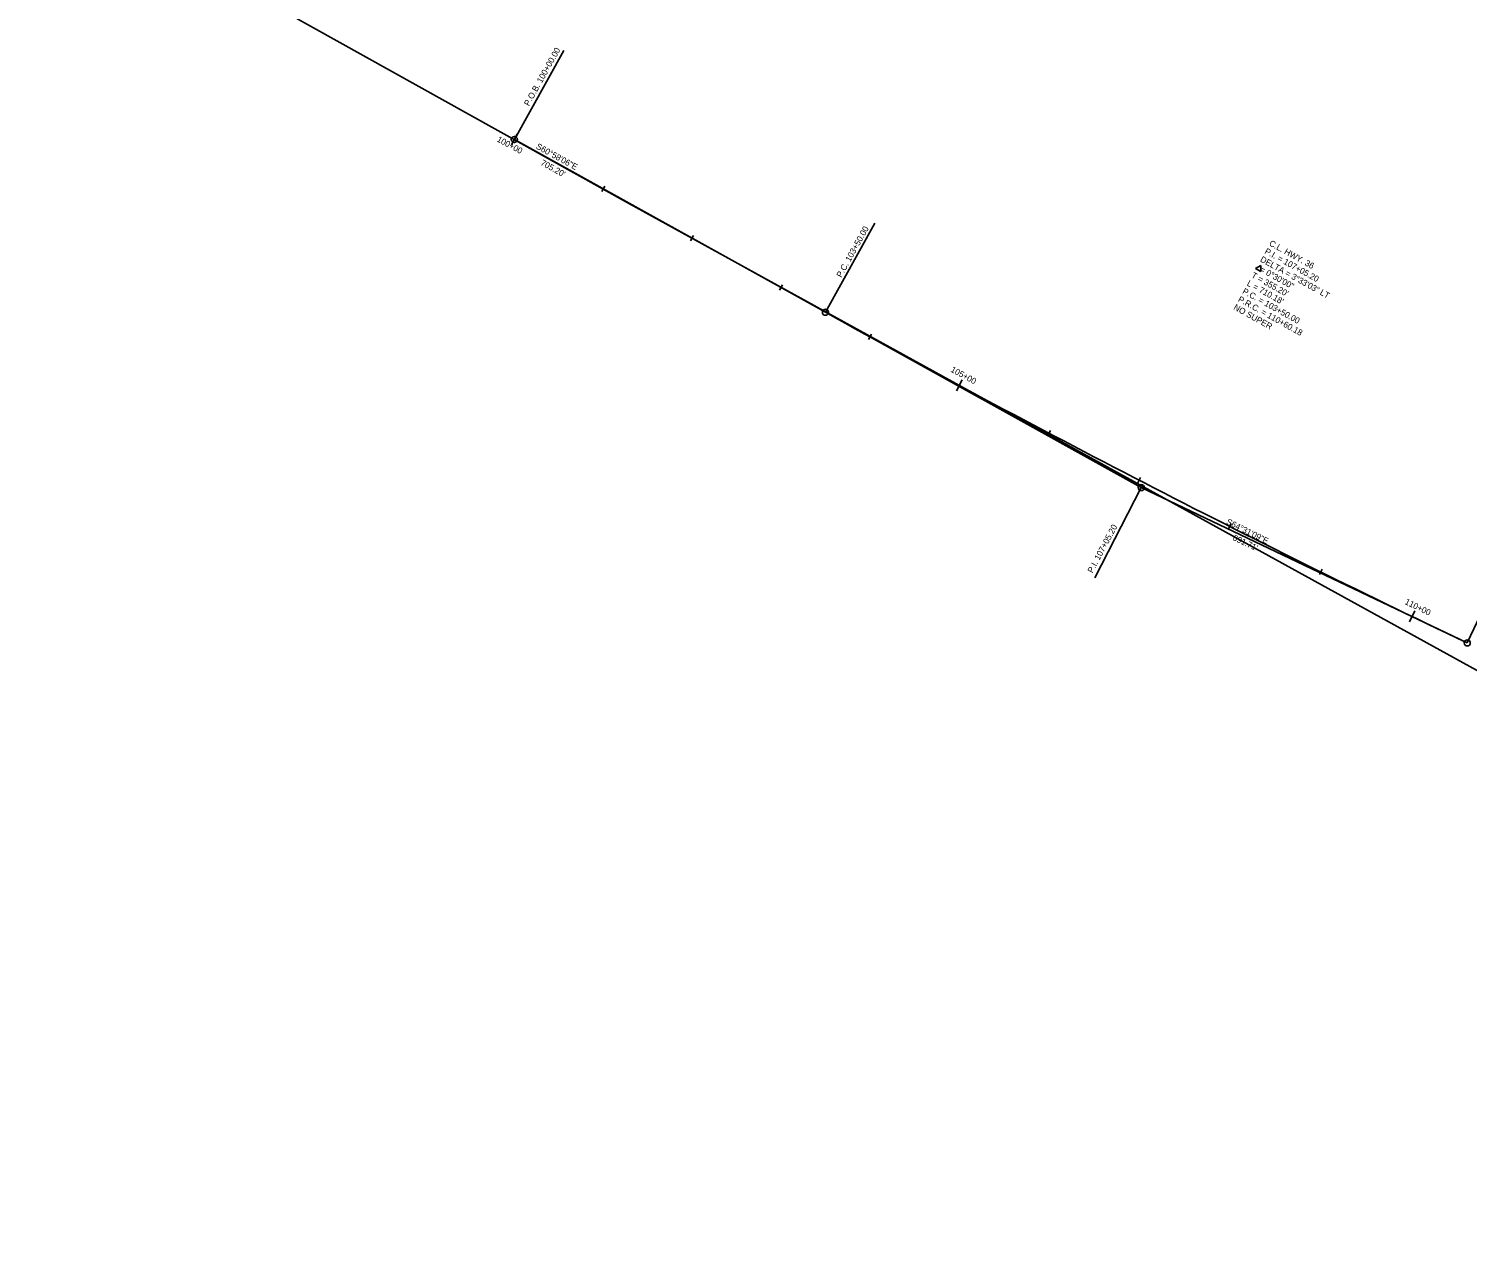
# Model space of a CAD drawing. Extents: x 1451272 to 1457767, y 301145 to 304591.
# Drawn here: x 1452687 to 1454102, y 302567 to 303775 of the extents above; entities that cross this region are included whole.
import ezdxf

# ---------------------------------------------------------------- set-up
doc = ezdxf.new("R2010")
doc.units = 0
for name, color, linetype in [('CL_Highway_1', 7, 'Continuous'), ('CL_Highway_1_text', 7, 'Continuous'), ('CL_Tangent', 7, 'Continuous'), ('CL_Tangent_Length', 7, 'Continuous'), ('CurveData_100', 7, 'Continuous'), ('PCPT_100_CL_ALT1', 7, 'Continuous'), ('PCPT_100_CL_Annot', 7, 'Continuous'), ('PI_100_CL_ALT1', 7, 'Continuous'), ('PI_100_CL_Annot', 7, 'Continuous'), ('Point_CL_Highway_2', 7, 'Continuous'), ('RD_Exist_CL', 7, 'Continuous'), ('STA_100_CL', 7, 'Continuous'), ('TICK_100_CL', 7, 'Continuous')]:
    doc.layers.add(name, color=color, linetype=linetype)

msp = doc.modelspace()

# ---------------------------------------------------------------- linework, layer by layer
at = {"layer": 'CL_Highway_1'}
msp.add_line((1453164.7, 303666.6), (1453470.7, 303496.7), dxfattribs=at)
msp.add_line((1453164.7, 303666.6), (1453470.7, 303496.7), dxfattribs=at)
msp.add_line((1453164.7, 303666.6), (1453470.7, 303496.7), dxfattribs=at)
msp.add_line((1453164.7, 303666.6), (1453470.7, 303496.7), dxfattribs=at)
msp.add_line((1453164.7, 303666.6), (1453470.7, 303496.7), dxfattribs=at)
msp.add_line((1453164.7, 303666.6), (1453470.7, 303496.7), dxfattribs=at)
msp.add_line((1453164.7, 303666.6), (1453470.7, 303496.7), dxfattribs=at)
msp.add_arc((1459031.8, 313516), 11459.2, 240.9683, 244.5192, dxfattribs=at)
msp.add_arc((1459031.8, 313516), 11459.2, 240.9683, 244.5192, dxfattribs=at)
msp.add_arc((1459031.8, 313516), 11459.2, 240.9683, 244.5192, dxfattribs=at)
msp.add_arc((1459031.8, 313516), 11459.2, 240.9683, 244.5192, dxfattribs=at)
msp.add_arc((1459031.8, 313516), 11459.2, 240.9683, 244.5192, dxfattribs=at)
msp.add_arc((1459031.8, 313516), 11459.2, 240.9683, 244.5192, dxfattribs=at)
msp.add_arc((1459031.8, 313516), 11459.2, 240.9683, 244.5192, dxfattribs=at)
at = {"layer": 'CL_Tangent'}
for p, q in [((1453470.7, 303496.7), (1453781.3, 303324.3)), ((1453781.3, 303324.3), (1454102, 303171.5))]:
    msp.add_line(p, q, dxfattribs=at)
for centre in [(1453164.7, 303666.6), (1453470.7, 303496.7), (1453781.3, 303324.3), (1454102, 303171.5)]:
    msp.add_circle(centre, 3, dxfattribs=at)
at = {"layer": 'CurveData_100'}
for p, q in [((1453898.8, 303542.8), (1453893.7, 303539.7)), ((1453893.7, 303539.7), (1453898.9, 303536.8)), ((1453898.8, 303542.8), (1453898.9, 303536.8))]:
    msp.add_line(p, q, dxfattribs=at)
at = {"layer": 'PCPT_100_CL_ALT1'}
for points in [[(1453164.7, 303666.6), (1453213.2, 303754)], [(1453470.7, 303496.7), (1453519.3, 303584.2)], [(1454102, 303171.5), (1454145, 303261.8)]]:
    msp.add_lwpolyline(points, dxfattribs=at)
at = {"layer": 'PI_100_CL_ALT1'}
msp.add_lwpolyline([(1453781.3, 303324.3), (1453735.5, 303235.4)], dxfattribs=at)
at = {"layer": 'Point_CL_Highway_2'}
for centre in [(1453164.7, 303666.6), (1453164.7, 303666.6), (1453470.7, 303496.7), (1453470.7, 303496.7), (1454102, 303171.5), (1454102, 303171.5), (1454102, 303171.5)]:
    msp.add_circle(centre, 3, dxfattribs=at)
at = {"layer": 'RD_Exist_CL'}
for p, q in [((1451779.1, 304438.6), (1453278, 303603.4)), ((1453278, 303603.4), (1455158.9, 302567.4))]:
    msp.add_line(p, q, dxfattribs=at)
at = {"layer": 'TICK_100_CL'}
for points in [[(1453167.6, 303671.8), (1453161.8, 303661.3)], [(1453253.6, 303620.7), (1453250.7, 303615.4)], [(1453341, 303572.1), (1453338.1, 303566.9)], [(1453428.5, 303523.6), (1453425.6, 303518.4)], [(1453516, 303475.2), (1453513.1, 303469.9)], [(1453605.2, 303430.1), (1453599.5, 303419.5)], [(1453692, 303380.4), (1453689.2, 303375.1)], [(1453780.7, 303334.2), (1453777.9, 303328.9)], [(1453869.7, 303288.8), (1453867, 303283.4)], [(1453959.2, 303244.1), (1453956.5, 303238.8)], [(1454050.3, 303203), (1454045.1, 303192.2)]]:
    msp.add_lwpolyline(points, dxfattribs=at)

# ---------------------------------------------------------------- texts
at = {"layer": 'CL_Highway_1_text'}
for s, rotation, p in [('S60%%d58\'06"E', 331.1834, (1453185.4, 303658)), ('S64%%d31\'09"E', 333.4069, (1453864.4, 303288.7))]:
    msp.add_text(s, height=6, rotation=rotation, dxfattribs=at).set_placement(p)
at = {"layer": 'CL_Tangent_Length'}
for s, rotation, p in [("705.20'", 331.1834, (1453189.9, 303641.9)), ("691.71'", 334.7804, (1453870.6, 303272.9))]:
    msp.add_text(s, height=6, rotation=rotation, dxfattribs=at).set_placement(p)
at = {"layer": 'CurveData_100'}
for s, p in [('P.I. = 107+05.20', (1453902.1, 303554.9)), ('C.L. HWY. 36', (1453906.5, 303562.8)), ('DELTA = 3%%d33\'03" LT', (1453897.7, 303547)), ("T = 355.20'", (1453889, 303531.3)), ('  = 0%%d30\'00"', (1453893.4, 303539.2)), ('P.C. = 103+50.00', (1453880.2, 303515.6)), ("L = 710.18'", (1453884.6, 303523.4)), ('NO SUPER', (1453871.5, 303499.8)), ('P.R.C. = 110+60.18', (1453875.9, 303507.7))]:
    msp.add_text(s, height=6, rotation=330.951, dxfattribs=at).set_placement(p)
at = {"layer": 'PCPT_100_CL_Annot'}
for s, p in [('P.O.B. 100+00.00', (1453179, 303699)), ('P.C. 103+50.00', (1453486.3, 303530.3))]:
    msp.add_text(s, height=6, rotation=60.8154, dxfattribs=at).set_placement(p)
at = {"layer": 'PI_100_CL_Annot'}
msp.add_text('P.I. 107+05.20', height=6, rotation=61.966, dxfattribs=at).set_placement((1453733.4, 303239.7))
at = {"layer": 'STA_100_CL'}
for s, rotation, p in [('100+00', 331.593, (1453146.9, 303665)), ('105+00', 331.593, (1453593.3, 303438.5)), ('110+00', 333.754, (1454040, 303210))]:
    msp.add_text(s, height=6, rotation=rotation, dxfattribs=at).set_placement(p)

doc.saveas('drawing.dxf')
